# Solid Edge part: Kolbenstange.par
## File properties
Username: bmolnar
Dokumentum tartalom típus: 0
Author: bmolnar
Last saved by: bmolnar
Revision: 79
Sűrűség: 0,000 kg/m^3
Pontosság: 0,990
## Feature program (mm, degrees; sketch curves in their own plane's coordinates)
base feature "unnamed BaseFeature 1"
sketch for "Furat_1" plane through (-10, 0, 0) normal (-1, 0, 0) x-axis (0, 1, 0)
  hole centre (0, 0) bore radius 2.4585
hole "Furat_1" nominal diameter 6 finite  ThreadDepth = 15 mm; StartChamferOffset = 0.7 mm; StartChamferAngle = 45 deg; VBottomAngle = 118 deg
sketch for "Kihúzás_1" plane through (23.5, 0, 0) normal (1, 0, 0) x-axis (0, -1, 0)
  circle centre (0, 0) radius 12.5
extrude "Kihúzás_1" add finite 14 along +normal
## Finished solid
Body 1: solid body, 14 faces, 20 edges, 8 vertices.
  Faces by surface: plane 7, cylinder 4, cone 2, torus 1
  Edges by curve: circle 10, line 6, ellipse 2, intersection 2
Bounding box of the edges (mm; curved faces can reach further): 47.500 x 25.000 x 25.000, from (-10, -12.5, -12.5) to (37.5, 12.5, 12.5).
Cylindrical faces by radius (mm): R2.4585 x2, R5 x1, R12.5 x1
Conical faces (half-angle, radius in mm at the cone's reference point): 45 deg R3.1585 x1, 59 deg R2.4585 x1
Toroidal faces (ring radius, tube radius in mm): R3.8 r1.2 x1
Planar faces by outward normal: +x 1, +z 1, -x 2, -z 1, oblique 2
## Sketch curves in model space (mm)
circle centre (23.5, 0, 0) radius 12.5
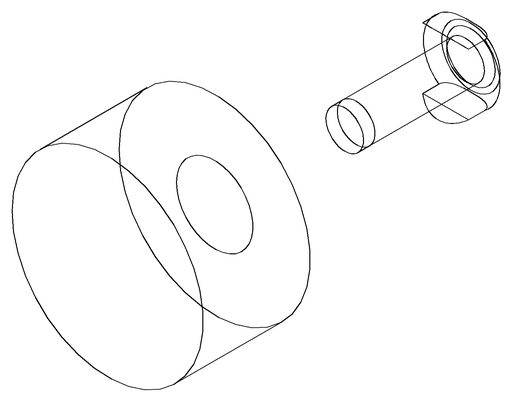
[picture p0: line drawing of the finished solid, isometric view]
